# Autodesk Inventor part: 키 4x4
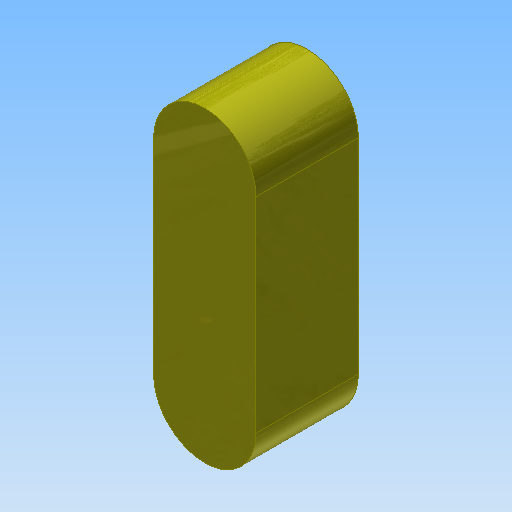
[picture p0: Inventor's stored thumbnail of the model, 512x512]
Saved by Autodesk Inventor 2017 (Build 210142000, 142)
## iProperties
Created: 2015-12
Part Number: 키 4x4
Document SubType Name: Modeling
Designer: mdu
Density: 7.86 g/cm^3
Material: 강철, 연강
Appearance: 노란색
Author: mdu
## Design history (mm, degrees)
sketch "스케치1"
  geometry: L1 (-2, -10)-(-2, -2) reference; L2 (2, -2)-(2, -10) reference; A1 r 2 centre (0, -2) between (2, -2) and (-2, -2) reference; A2 r 2 centre (0, -10) between (-2, -10) and (2, -10) reference; 1 further point
extrude "돌출1" new body sketch "스케치1" distance "d0" = 4; taper "d1" = 0 deg
node "솔리드1"
node "참조1"
